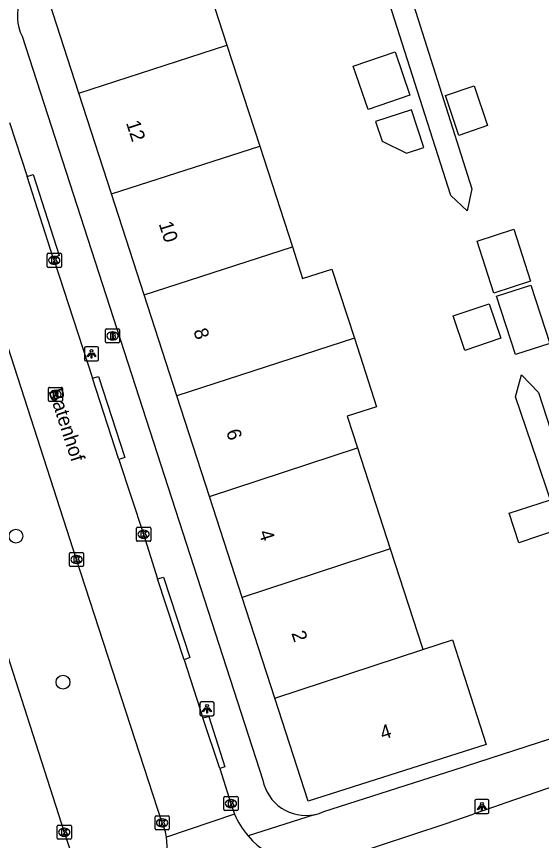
# Model space of a CAD drawing. Extents: x 159265 to 160143, y 383413 to 384319.
# Drawn here: x 159502.7 to 159539.9, y 383875.4 to 383933.7 of the extents above; entities that cross this region are included whole.
import ezdxf

# ---------------------------------------------------------------- set-up
doc = ezdxf.new("R2010")
doc.units = 0
for name, color, linetype in [('IMGEO_Boom', 7, 'Continuous'), ('IMGEO_Brandkraan', 7, 'Continuous'), ('IMGEO_Kolk', 7, 'Continuous'), ('IMGEO_Lichtpunt', 7, 'Continuous'), ('IMGEO_Muur', 7, 'Continuous'), ('IMGEO_Openbare_ruimte_label', 7, 'Continuous'), ('IMGEO_Pand', 7, 'Continuous'), ('IMGEO_Pand_nummerreeks', 7, 'Continuous'), ('IMGEO_Rijbaan_lokaal_open', 7, 'Continuous'), ('IMGEO_Rioolput', 7, 'Continuous'), ('IMGEO_Voetpad_open', 7, 'Continuous')]:
    doc.layers.add(name, color=color, linetype=linetype)

msp = doc.modelspace()

# ---------------------------------------------------------------- linework, layer by layer
at = {"layer": 'IMGEO_Boom'}
for centre in [(159502.661, 383896.928), (159505.992, 383886.591)]:
    msp.add_circle(centre, 0.489, dxfattribs=at)
at = {"layer": 'IMGEO_Brandkraan'}
for p, q in [((159508.997, 383910.68), (159508.997, 383911.532)), ((159509.072, 383911.606), (159509.924, 383911.606)), ((159509.485, 383911.386), (159509.51, 383911.386)), ((159509.998, 383911.532), (159509.998, 383910.68)), ((159509.508, 383910.826), (159509.483, 383910.826)), ((159509.924, 383910.606), (159509.072, 383910.606))]:
    msp.add_line(p, q, dxfattribs=at)
for points in [[(159508.997, 383910.68), (159508.997, 383911.532)], [(159509.072, 383911.606), (159509.924, 383911.606)], [(159509.345, 383911.306), (159509.345, 383910.906), (159509.558, 383910.906)], [(159509.576, 383911.306), (159509.345, 383911.306)], [(159509.524, 383911.225), (159509.47, 383911.225), (159509.47, 383911.149)], [(159509.998, 383911.532), (159509.998, 383910.68)], [(159509.47, 383911.149), (159509.523, 383911.149)], [(159509.532, 383911.073), (159509.47, 383911.073), (159509.47, 383910.992)], [(159509.47, 383910.992), (159509.532, 383910.992)], [(159509.924, 383910.606), (159509.072, 383910.606)]]:
    msp.add_lwpolyline(points, dxfattribs=at)
for centre, radius, start, end in [((159509.074, 383911.53), 0.0765, 91.55205, 178.44795), ((159509.074, 383911.53), 0.0765, 91.55205, 178.44795), ((159509.525, 383911.187), 0.0379, 267.82845, 90.93552), ((159509.58, 383911.161), 0.145, 59.4692, 91.53667), ((159509.605, 383911.208), 0.0922, 285.51372, 58.15012), ((159509.922, 383911.53), 0.0765, 1.55205, 88.44795), ((159509.922, 383911.53), 0.0765, 1.55205, 88.44795), ((159509.074, 383910.682), 0.0765, 181.55205, 268.44795), ((159509.074, 383910.682), 0.0765, 181.55205, 268.44795), ((159509.533, 383911.032), 0.0404, 269.87594, 90.50774), ((159509.564, 383911.157), 0.251, 268.66757, 293.53466), ((159509.61, 383911.016), 0.105, 301.31148, 78.98903), ((159509.922, 383910.682), 0.0765, 271.55205, 358.44795), ((159509.922, 383910.682), 0.0765, 271.55205, 358.44795)]:
    msp.add_arc(centre, radius, start, end, dxfattribs=at)
for centre, major_axis, ratio, start_param, end_param in [((159509.484, 383911.106), (-0.387, 0.002), 0.722429, 4.712389, 7.853982), ((159509.509, 383911.106), (-0.39, 0.002), 0.717154, 1.570796, 4.712389)]:
    msp.add_ellipse(centre, major_axis=major_axis, ratio=ratio, start_param=start_param, end_param=end_param, dxfattribs=at)
at = {"layer": 'IMGEO_Kolk'}
for p, q in [((159504.875, 383916.029), (159504.875, 383916.881)), ((159504.95, 383916.955), (159505.802, 383916.955)), ((159505.363, 383916.735), (159505.388, 383916.735)), ((159505.876, 383916.881), (159505.876, 383916.029)), ((159505.802, 383915.955), (159504.95, 383915.955)), ((159505.386, 383916.175), (159505.361, 383916.175)), ((159511.195, 383896.636), (159511.195, 383897.488)), ((159511.27, 383897.562), (159512.122, 383897.562)), ((159511.683, 383897.342), (159511.708, 383897.342)), ((159512.196, 383897.488), (159512.196, 383896.636)), ((159511.706, 383896.782), (159511.681, 383896.782)), ((159512.122, 383896.562), (159511.27, 383896.562)), ((159506.449, 383894.85), (159506.449, 383895.702)), ((159506.524, 383895.776), (159507.376, 383895.776)), ((159506.937, 383895.556), (159506.962, 383895.556)), ((159507.45, 383895.702), (159507.45, 383894.85)), ((159506.96, 383894.996), (159506.935, 383894.996)), ((159507.376, 383894.776), (159506.524, 383894.776)), ((159517.378, 383877.568), (159517.378, 383878.42)), ((159517.453, 383878.494), (159518.305, 383878.494)), ((159517.866, 383878.274), (159517.891, 383878.274)), ((159518.379, 383878.42), (159518.379, 383877.568)), ((159518.305, 383877.494), (159517.453, 383877.494)), ((159517.889, 383877.714), (159517.864, 383877.714)), ((159512.506, 383876.202), (159512.506, 383877.054)), ((159512.581, 383877.128), (159513.433, 383877.128)), ((159512.994, 383876.908), (159513.019, 383876.908)), ((159513.507, 383877.054), (159513.507, 383876.202)), ((159505.582, 383875.538), (159505.582, 383876.39)), ((159505.657, 383876.464), (159506.509, 383876.464)), ((159506.07, 383876.244), (159506.095, 383876.244)), ((159506.583, 383876.39), (159506.583, 383875.538)), ((159513.017, 383876.348), (159512.992, 383876.348)), ((159506.093, 383875.684), (159506.068, 383875.684)), ((159513.433, 383876.128), (159512.581, 383876.128)), ((159506.509, 383875.464), (159505.657, 383875.464))]:
    msp.add_line(p, q, dxfattribs=at)
for points in [[(159504.875, 383916.029), (159504.875, 383916.881)], [(159504.95, 383916.955), (159505.802, 383916.955)], [(159505.196, 383916.655), (159505.319, 383916.655), (159505.319, 383916.504), (159505.449, 383916.655), (159505.613, 383916.655), (159505.467, 383916.504), (159505.62, 383916.255), (159505.468, 383916.255), (159505.383, 383916.419), (159505.319, 383916.352), (159505.319, 383916.255), (159505.196, 383916.255), (159505.196, 383916.655)], [(159505.876, 383916.881), (159505.876, 383916.029)], [(159505.802, 383915.955), (159504.95, 383915.955)], [(159511.195, 383896.636), (159511.195, 383897.488)], [(159511.27, 383897.562), (159512.122, 383897.562)], [(159511.516, 383897.262), (159511.639, 383897.262), (159511.639, 383897.111), (159511.769, 383897.262), (159511.933, 383897.262), (159511.787, 383897.111), (159511.94, 383896.862), (159511.788, 383896.862), (159511.703, 383897.026), (159511.639, 383896.959), (159511.639, 383896.862), (159511.516, 383896.862), (159511.516, 383897.262)], [(159512.196, 383897.488), (159512.196, 383896.636)], [(159512.122, 383896.562), (159511.27, 383896.562)], [(159506.449, 383894.85), (159506.449, 383895.702)], [(159506.524, 383895.776), (159507.376, 383895.776)], [(159506.77, 383895.476), (159506.893, 383895.476), (159506.893, 383895.325), (159507.023, 383895.476), (159507.187, 383895.476), (159507.041, 383895.325), (159507.194, 383895.076), (159507.042, 383895.076), (159506.957, 383895.24), (159506.893, 383895.173), (159506.893, 383895.076), (159506.77, 383895.076), (159506.77, 383895.476)], [(159507.45, 383895.702), (159507.45, 383894.85)], [(159507.376, 383894.776), (159506.524, 383894.776)], [(159517.378, 383877.568), (159517.378, 383878.42)], [(159517.453, 383878.494), (159518.305, 383878.494)], [(159517.699, 383878.194), (159517.822, 383878.194), (159517.822, 383878.043), (159517.952, 383878.194), (159518.116, 383878.194), (159517.97, 383878.043), (159518.123, 383877.794), (159517.971, 383877.794), (159517.886, 383877.958), (159517.822, 383877.891), (159517.822, 383877.794), (159517.699, 383877.794), (159517.699, 383878.194)], [(159518.379, 383878.42), (159518.379, 383877.568)], [(159518.305, 383877.494), (159517.453, 383877.494)], [(159512.506, 383876.202), (159512.506, 383877.054)], [(159512.581, 383877.128), (159513.433, 383877.128)], [(159512.827, 383876.828), (159512.95, 383876.828), (159512.95, 383876.677), (159513.08, 383876.828), (159513.244, 383876.828), (159513.098, 383876.677), (159513.251, 383876.428), (159513.099, 383876.428), (159513.014, 383876.592), (159512.95, 383876.525), (159512.95, 383876.428), (159512.827, 383876.428), (159512.827, 383876.828)], [(159513.507, 383877.054), (159513.507, 383876.202)], [(159505.582, 383875.538), (159505.582, 383876.39)], [(159505.657, 383876.464), (159506.509, 383876.464)], [(159506.583, 383876.39), (159506.583, 383875.538)], [(159505.903, 383876.164), (159506.026, 383876.164), (159506.026, 383876.013), (159506.156, 383876.164), (159506.32, 383876.164), (159506.174, 383876.013), (159506.327, 383875.764), (159506.175, 383875.764), (159506.09, 383875.928), (159506.026, 383875.861), (159506.026, 383875.764), (159505.903, 383875.764), (159505.903, 383876.164)], [(159513.433, 383876.128), (159512.581, 383876.128)], [(159506.509, 383875.464), (159505.657, 383875.464)]]:
    msp.add_lwpolyline(points, dxfattribs=at)
for centre, start, end in [((159504.952, 383916.879), 91.55205, 178.44795), ((159504.952, 383916.879), 91.55205, 178.44795), ((159505.8, 383916.879), 1.55205, 88.44795), ((159505.8, 383916.879), 1.55205, 88.44795), ((159504.952, 383916.031), 181.55205, 268.44795), ((159504.952, 383916.031), 181.55205, 268.44795), ((159505.8, 383916.031), 271.55205, 358.44795), ((159505.8, 383916.031), 271.55205, 358.44795), ((159511.272, 383897.486), 91.55205, 178.44795), ((159511.272, 383897.486), 91.55205, 178.44795), ((159512.12, 383897.486), 1.55205, 88.44795), ((159512.12, 383897.486), 1.55205, 88.44795), ((159511.272, 383896.638), 181.55205, 268.44795), ((159511.272, 383896.638), 181.55205, 268.44795), ((159512.12, 383896.638), 271.55205, 358.44795), ((159512.12, 383896.638), 271.55205, 358.44795), ((159506.526, 383895.7), 91.55205, 178.44795), ((159506.526, 383895.7), 91.55205, 178.44795), ((159507.374, 383895.7), 1.55205, 88.44795), ((159507.374, 383895.7), 1.55205, 88.44795), ((159506.526, 383894.852), 181.55205, 268.44795), ((159506.526, 383894.852), 181.55205, 268.44795), ((159507.374, 383894.852), 271.55205, 358.44795), ((159507.374, 383894.852), 271.55205, 358.44795), ((159517.455, 383878.418), 91.55205, 178.44795), ((159517.455, 383878.418), 91.55205, 178.44795), ((159518.303, 383878.418), 1.55205, 88.44795), ((159518.303, 383878.418), 1.55205, 88.44795), ((159517.455, 383877.57), 181.55205, 268.44795), ((159517.455, 383877.57), 181.55205, 268.44795), ((159518.303, 383877.57), 271.55205, 358.44795), ((159518.303, 383877.57), 271.55205, 358.44795), ((159512.583, 383877.052), 91.55205, 178.44795), ((159512.583, 383877.052), 91.55205, 178.44795), ((159513.431, 383877.052), 1.55205, 88.44795), ((159513.431, 383877.052), 1.55205, 88.44795), ((159505.659, 383876.388), 91.55205, 178.44795), ((159505.659, 383876.388), 91.55205, 178.44795), ((159506.507, 383876.388), 1.55205, 88.44795), ((159506.507, 383876.388), 1.55205, 88.44795), ((159512.583, 383876.204), 181.55205, 268.44795), ((159512.583, 383876.204), 181.55205, 268.44795), ((159513.431, 383876.204), 271.55205, 358.44795), ((159513.431, 383876.204), 271.55205, 358.44795), ((159505.659, 383875.54), 181.55205, 268.44795), ((159505.659, 383875.54), 181.55205, 268.44795), ((159506.507, 383875.54), 271.55205, 358.44795), ((159506.507, 383875.54), 271.55205, 358.44795)]:
    msp.add_arc(centre, 0.0765, start, end, dxfattribs=at)
for centre, major_axis, ratio, start_param, end_param in [((159505.362, 383916.455), (-0.387, 0.002), 0.722429, 4.712389, 7.853982), ((159505.387, 383916.455), (-0.39, 0.002), 0.717154, 1.570796, 4.712389), ((159511.682, 383897.062), (-0.387, 0.002), 0.722429, 4.712389, 7.853982), ((159511.707, 383897.062), (-0.39, 0.002), 0.717154, 1.570796, 4.712389), ((159506.936, 383895.276), (-0.387, 0.002), 0.722429, 4.712389, 7.853982), ((159506.961, 383895.276), (-0.39, 0.002), 0.717154, 1.570796, 4.712389), ((159517.865, 383877.994), (-0.387, 0.002), 0.722429, 4.712389, 7.853982), ((159517.89, 383877.994), (-0.39, 0.002), 0.717154, 1.570796, 4.712389), ((159512.993, 383876.628), (-0.387, 0.002), 0.722429, 4.712389, 7.853982), ((159513.018, 383876.628), (-0.39, 0.002), 0.717154, 1.570796, 4.712389), ((159506.069, 383875.964), (-0.387, 0.002), 0.722429, 4.712389, 7.853982), ((159506.094, 383875.964), (-0.39, 0.002), 0.717154, 1.570796, 4.712389)]:
    msp.add_ellipse(centre, major_axis=major_axis, ratio=ratio, start_param=start_param, end_param=end_param, dxfattribs=at)
at = {"layer": 'IMGEO_Lichtpunt'}
for p, q in [((159507.515, 383910.245), (159507.515, 383909.438)), ((159507.515, 383910.245), (159507.515, 383909.438)), ((159508.417, 383910.34), (159507.609, 383910.34)), ((159508.417, 383910.34), (159507.609, 383910.34)), ((159508.511, 383909.438), (159508.511, 383910.245)), ((159508.511, 383909.438), (159508.511, 383910.245)), ((159507.609, 383909.344), (159508.417, 383909.344)), ((159507.609, 383909.344), (159508.417, 383909.344)), ((159515.684, 383885.105), (159515.684, 383884.298)), ((159515.684, 383885.105), (159515.684, 383884.298)), ((159516.586, 383885.2), (159515.778, 383885.2)), ((159516.586, 383885.2), (159515.778, 383885.2)), ((159516.68, 383884.298), (159516.68, 383885.105)), ((159516.68, 383884.298), (159516.68, 383885.105)), ((159515.778, 383884.204), (159516.586, 383884.204)), ((159515.778, 383884.204), (159516.586, 383884.204)), ((159535.141, 383878.183), (159535.141, 383877.376)), ((159535.141, 383878.183), (159535.141, 383877.376)), ((159536.043, 383878.278), (159535.235, 383878.278)), ((159536.043, 383878.278), (159535.235, 383878.278)), ((159536.137, 383877.376), (159536.137, 383878.183)), ((159536.137, 383877.376), (159536.137, 383878.183)), ((159535.235, 383877.282), (159536.043, 383877.282)), ((159535.235, 383877.282), (159536.043, 383877.282))]:
    msp.add_line(p, q, dxfattribs=at)
for points in [[(159507.889, 383909.909), (159507.928, 383909.881), (159507.74, 383909.619), (159507.702, 383909.646), (159507.889, 383909.909)], [(159507.991, 383909.861), (159508.038, 383909.861), (159508.038, 383909.539), (159507.991, 383909.539), (159507.991, 383909.861)], [(159508.101, 383909.881), (159508.139, 383909.908), (159508.326, 383909.646), (159508.287, 383909.618), (159508.101, 383909.881)], [(159516.058, 383884.769), (159516.097, 383884.741), (159515.909, 383884.479), (159515.871, 383884.506), (159516.058, 383884.769)], [(159516.16, 383884.721), (159516.207, 383884.721), (159516.207, 383884.399), (159516.16, 383884.399), (159516.16, 383884.721)], [(159516.27, 383884.741), (159516.308, 383884.768), (159516.495, 383884.506), (159516.456, 383884.478), (159516.27, 383884.741)], [(159535.515, 383877.847), (159535.554, 383877.819), (159535.366, 383877.557), (159535.328, 383877.584), (159535.515, 383877.847)], [(159535.617, 383877.799), (159535.664, 383877.799), (159535.664, 383877.477), (159535.617, 383877.477), (159535.617, 383877.799)], [(159535.727, 383877.819), (159535.765, 383877.846), (159535.952, 383877.584), (159535.913, 383877.556), (159535.727, 383877.819)]]:
    msp.add_lwpolyline(points, dxfattribs=at)
for centre in [(159508.014, 383910.043), (159516.183, 383884.903), (159535.64, 383877.981)]:
    msp.add_circle(centre, 0.0994, dxfattribs=at)
for centre, start, end in [((159507.609, 383910.245), 90, 180), ((159507.609, 383910.245), 90, 180), ((159508.417, 383910.245), 0, 90), ((159508.417, 383910.245), 0, 90), ((159507.609, 383909.438), 180, 270), ((159507.609, 383909.438), 180, 270), ((159508.417, 383909.438), 270, 0), ((159508.417, 383909.438), 270, 360), ((159515.778, 383885.105), 90, 180), ((159515.778, 383885.105), 90, 180), ((159516.586, 383885.105), 0, 90), ((159516.586, 383885.105), 0, 90), ((159515.778, 383884.298), 180, 270), ((159515.778, 383884.298), 180, 270), ((159516.586, 383884.298), 270, 0), ((159516.586, 383884.298), 270, 360), ((159535.235, 383878.183), 90, 180), ((159535.235, 383878.183), 90, 180), ((159536.043, 383878.183), 0, 90), ((159536.043, 383878.183), 0, 90), ((159535.235, 383877.376), 180, 270), ((159535.235, 383877.376), 180, 270), ((159536.043, 383877.376), 270, 0), ((159536.043, 383877.376), 270, 360)]:
    msp.add_arc(centre, 0.0946, start, end, dxfattribs=at)
at = {"layer": 'IMGEO_Muur'}
msp.add_lwpolyline([(159533.665, 383880.391), (159557.611, 383888.144)], dxfattribs=at)
at = {"layer": 'IMGEO_Pand'}
for points in [[(159507.115, 383928.284), (159504.741, 383935.614), (159515.195, 383939.054), (159516.748, 383934.301), (159517.596, 383931.686)], [(159507.115, 383928.284), (159517.596, 383931.686)], [(159517.596, 383931.686), (159519.911, 383924.542)], [(159527.579, 383927.143), (159526.538, 383930.204), (159529.501, 383931.212), (159530.542, 383928.151), (159527.579, 383927.143)], [(159534.013, 383925.305), (159533.071, 383928.133), (159535.1, 383928.809), (159536.036, 383926.003), (159534.013, 383925.305)], [(159509.423, 383921.158), (159507.115, 383928.284)], [(159531.523, 383924.447), (159530.661, 383927.117), (159528.115, 383926.296), (159528.571, 383924.883), (159530.297, 383924.052), (159531.523, 383924.447)], [(159509.423, 383921.158), (159519.911, 383924.542)], [(159519.911, 383924.542), (159522.224, 383917.407)], [(159511.734, 383914.025), (159509.423, 383921.158)], [(159536.077, 383915.389), (159535.294, 383917.81), (159537.901, 383918.654), (159539.088, 383914.985), (159536.484, 383914.142), (159536.077, 383915.389)], [(159511.734, 383914.025), (159522.224, 383917.407)], [(159522.224, 383917.407), (159522.951, 383915.165), (159525.025, 383915.837), (159526.61, 383910.947)], [(159536.668, 383913.918), (159539.099, 383914.705), (159540.438, 383910.566), (159538.007, 383909.78), (159536.668, 383913.918)], [(159514.053, 383906.864), (159511.734, 383914.025)], [(159536.966, 383910.935), (159534.423, 383910.081), (159533.604, 383912.519), (159536.147, 383913.373), (159536.966, 383910.935)], [(159526.61, 383910.947), (159514.053, 383906.864)], [(159526.61, 383910.947), (159528.185, 383906.087), (159526.111, 383905.415), (159526.839, 383903.17)], [(159516.363, 383899.732), (159514.053, 383906.864)], [(159516.363, 383899.732), (159526.839, 383903.17)], [(159526.839, 383903.17), (159529.154, 383896.026)], [(159518.68, 383892.58), (159516.363, 383899.732)], [(159541.181, 383897.44), (159538.261, 383896.456), (159537.556, 383898.547), (159540.487, 383899.497)], [(159529.154, 383896.026), (159518.68, 383892.58)], [(159529.154, 383896.026), (159531.41, 383889.065), (159531.466, 383888.893)], [(159520.991, 383885.447), (159518.68, 383892.58)], [(159531.466, 383888.893), (159533.556, 383889.581), (159534.413, 383886.938), (159535.94, 383882.177), (159523.348, 383878.169), (159520.991, 383885.447)], [(159520.991, 383885.447), (159531.466, 383888.893)]]:
    msp.add_lwpolyline(points, dxfattribs=at)
at = {"layer": 'IMGEO_Rijbaan_lokaal_open'}
for points in [[(159513.316, 383875.623), (159513.238, 383875.992), (159513.009, 383876.629), (159506.951, 383895.276), (159500, 383916.735), (159494.88, 383932.541), (159494.602, 383933.425)], [(159488.178, 383931.3), (159488.299, 383930.857), (159489.285, 383927.789), (159494.989, 383910.203), (159499.83, 383895.339), (159500, 383894.812), (159506.082, 383875.964), (159506.782, 383873.85), (159506.91, 383873.565)], [(159502.214, 383926.219), (159503.456, 383922.4)], [(159505.289, 383916.639), (159503.456, 383922.4)], [(159505.289, 383916.639), (159505.376, 383916.455), (159508.082, 383908.102)], [(159509.941, 383902.365), (159508.082, 383908.102)], [(159509.941, 383902.365), (159511.695, 383897.062), (159512.685, 383893.898)], [(159514.565, 383888.168), (159512.685, 383893.898)], [(159514.565, 383888.168), (159515.888, 383884.058)], [(159517.094, 383880.482), (159515.888, 383884.058)], [(159517.094, 383880.482), (159517.878, 383877.993), (159518.132, 383877.248)], [(159518.132, 383877.248), (159513.316, 383875.623)], [(159526.184, 383874.298), (159533.043, 383876.562), (159535.026, 383877.241)]]:
    msp.add_lwpolyline(points, dxfattribs=at)
for centre, radius, start, end in [((159611.747, 383663.024), 227.542, 106.51077, 109.70485), ((159523.497, 383879.498), 5.818, 202.75687, 220.78754), ((159509.948, 383875.107), 3.407, 206.90805, 8.71235), ((159523.466, 383879.482), 5.783, 220.86042, 291.53652)]:
    msp.add_arc(centre, radius, start, end, dxfattribs=at)
at = {"layer": 'IMGEO_Rioolput'}
for p, q in [((159504.96, 383906.537), (159504.96, 383907.389)), ((159505.035, 383907.463), (159505.887, 383907.463)), ((159505.448, 383907.243), (159505.473, 383907.243)), ((159505.961, 383907.389), (159505.961, 383906.537)), ((159505.471, 383906.683), (159505.446, 383906.683)), ((159505.887, 383906.463), (159505.035, 383906.463))]:
    msp.add_line(p, q, dxfattribs=at)
for points in [[(159504.96, 383906.537), (159504.96, 383907.389)], [(159505.035, 383907.463), (159505.887, 383907.463)], [(159505.549, 383907.161), (159505.297, 383907.163), (159505.297, 383906.763)], [(159505.961, 383907.389), (159505.961, 383906.537)], [(159505.297, 383906.763), (159505.421, 383906.763), (159505.421, 383906.925), (159505.432, 383906.925)], [(159505.475, 383907.082), (159505.421, 383907.082), (159505.421, 383907.001)], [(159505.421, 383907.001), (159505.473, 383907.001)], [(159505.479, 383906.896), (159505.55, 383906.763), (159505.69, 383906.763), (159505.625, 383906.889)], [(159505.887, 383906.463), (159505.035, 383906.463)]]:
    msp.add_lwpolyline(points, dxfattribs=at)
for centre, radius, start, end in [((159505.037, 383907.387), 0.0765, 91.55205, 178.44795), ((159505.037, 383907.387), 0.0765, 91.55205, 178.44795), ((159505.548, 383907.051), 0.109, 350.36119, 89.41601), ((159505.885, 383907.387), 0.0765, 1.55205, 88.44795), ((159505.885, 383907.387), 0.0765, 1.55205, 88.44795), ((159505.037, 383906.539), 0.0765, 181.55205, 268.44795), ((159505.037, 383906.539), 0.0765, 181.55205, 268.44795), ((159505.431, 383906.872), 0.0533, 26.02933, 88.69889), ((159505.457, 383907.19), 0.19, 274.7715, 282.96867), ((159505.481, 383906.986), 0.0964, 77.00612, 93.18647), ((159505.495, 383907.043), 0.0378, 276.66336, 79.67722), ((159505.546, 383907.051), 0.112, 277.58423, 350.98172), ((159505.53, 383906.836), 0.108, 29.51342, 73.79051), ((159505.885, 383906.539), 0.0765, 271.55205, 358.44795), ((159505.885, 383906.539), 0.0765, 271.55205, 358.44795)]:
    msp.add_arc(centre, radius, start, end, dxfattribs=at)
for centre, major_axis, ratio, start_param, end_param in [((159505.447, 383906.963), (-0.387, 0.002), 0.722429, 4.712389, 7.853982), ((159505.472, 383906.963), (-0.39, 0.002), 0.717154, 1.570796, 4.712389)]:
    msp.add_ellipse(centre, major_axis=major_axis, ratio=ratio, start_param=start_param, end_param=end_param, dxfattribs=at)
at = {"layer": 'IMGEO_Voetpad_open'}
for points in [[(159530.356, 383935.988), (159534.919, 383921.526), (159534.598, 383919.961), (159533.437, 383921.043), (159526.199, 383943.743)], [(159503.104, 383932.317), (159520.139, 383879.653)], [(159503.456, 383922.4), (159503.886, 383922.534), (159505.727, 383916.796), (159505.289, 383916.639)], [(159540.487, 383899.497), (159540.426, 383899.679), (159539.55, 383902.277), (159538.026, 383906.798), (159538.442, 383908.353), (159539.648, 383907.11), (159546.91, 383884.679)], [(159508.082, 383908.102), (159508.512, 383908.231), (159510.361, 383902.497), (159509.941, 383902.365)], [(159512.685, 383893.898), (159513.103, 383894.022), (159514.96, 383888.332), (159514.565, 383888.168)], [(159515.888, 383884.058), (159516.306, 383884.165), (159517.45, 383880.597), (159517.094, 383880.482)], [(159524.454, 383877.425), (159533.665, 383880.391), (159545.464, 383884.211)], [(159523.776, 383877.207), (159519.092, 383875.698)]]:
    msp.add_lwpolyline(points, dxfattribs=at)
for centre, radius, start, end in [((159505.905, 383933.747), 3.145, 110.58828, 207.04731), ((159523.174, 383880.238), 3.09, 190.91491, 281.24088), ((159523.189, 383880.197), 3.047, 281.11389, 294.53483)]:
    msp.add_arc(centre, radius, start, end, dxfattribs=at)

# ---------------------------------------------------------------- texts
at = {"layer": 'IMGEO_Openbare_ruimte_label'}
msp.add_text('Batenhof', height=1, rotation=288.05455, dxfattribs=at).set_placement((159504.95, 383907.207))
at = {"layer": 'IMGEO_Pand_nummerreeks'}
for s, rotation, p in [('12', 287.94764, (159510.441, 383926.193)), ('10', 287.94764, (159512.755, 383919.047)), ('8', 287.94764, (159515.209, 383911.47)), ('6', 287.94764, (159517.521, 383904.335)), ('4', 287.94764, (159519.834, 383897.195)), ('2', 287.94483, (159522.147, 383890.058)), ('4', 17.65856, (159528.617, 383882.49))]:
    msp.add_text(s, height=1, rotation=rotation, dxfattribs=at).set_placement(p)

doc.saveas('drawing.dxf')
